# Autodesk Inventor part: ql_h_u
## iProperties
Created: 2007-11
Part Number: ql_h_u
Document SubType Name: Modeling
Designer: martin
Manufacturer: Standard
Standards Organization: Custom
Author: martin
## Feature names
1. Extrusion2
